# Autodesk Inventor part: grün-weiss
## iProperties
Created: 2004-10
Part Number: grün-weiss
Document SubType Name: Modeling
Designer: sahrens
Manufacturer: Standard
Standards Organization: Custom
Author: sahrens
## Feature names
1. Extrusion1
2. Rundung2 [Fillet]
